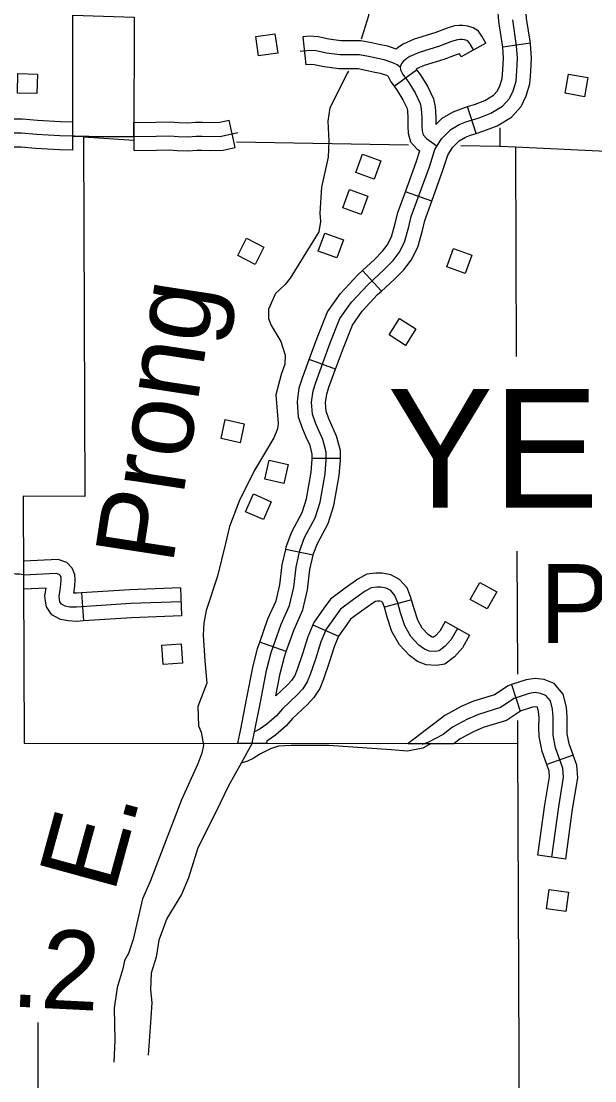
# Model space of a CAD drawing. Extents: x 1370130 to 1380143, y 377636 to 380256.
# Drawn here: x 1377471.8 to 1377557.8, y 379033.5 to 379192.2 of the extents above; entities that cross this region are included whole.
import ezdxf

# ---------------------------------------------------------------- set-up
doc = ezdxf.new("R2010")
doc.units = 0
for name, color, linetype in [('Level 32', 7, 'Continuous'), ('Level 34', 7, 'Continuous'), ('Level 35', 7, 'Continuous'), ('Level 4', 7, 'Continuous'), ('Level 48', 7, 'Continuous'), ('Level 5', 7, 'Continuous'), ('Level 56', 7, 'Continuous'), ('Level 6', 7, 'Continuous')]:
    doc.layers.add(name, color=color, linetype=linetype)

msp = doc.modelspace()

# ---------------------------------------------------------------- linework, layer by layer
at = {"layer": 'Level 32'}
for p, q in [((1377513.99, 379189.81), (1377514.45, 379185.63)), ((1377541.41, 379188.89), (1377537.74, 379186.86)), ((1377548.1, 379188.9), (1377543.95, 379188.27)), ((1377527.68, 379182.43), (1377531.06, 379184.91)), ((1377539.97, 379175.38), (1377538.7, 379179.39)), ((1377503.89, 379173.26), (1377502.97, 379177.36)), ((1377533.32, 379165.21), (1377529.37, 379166.65)), ((1377525.8, 379151.76), (1377522.97, 379154.87)), ((1377518.92, 379140.09), (1377514.97, 379141.54)), ((1377519.63, 379126.7), (1377515.43, 379126.7)), ((1377515.54, 379112.2), (1377511.44, 379113.09)), ((1377480.86, 379106.57), (1377481.14, 379102.38)), ((1377495.68, 379107.35), (1377495.85, 379103.15)), ((1377530.3, 379105.54), (1377526.25, 379104.43)), ((1377515.52, 379101.78), (1377519.36, 379100.09)), ((1377535.35, 379102.29), (1377539, 379100.22)), ((1377511.53, 379097.79), (1377507.56, 379099.18)), ((1377545.27, 379092.84), (1377546.57, 379088.84)), ((1377554.52, 379082.27), (1377550.57, 379080.87)), ((1377553.4, 379066.71), (1377549.24, 379067.28))]:
    msp.add_line(p, q, dxfattribs=at)
for points in [[(1377543.95, 379188.27), (1377543.36, 379192.13), (1377543.17, 379194.94), (1377543.22, 379197.67), (1377543.5, 379201.64), (1377543.76, 379203.58)], [(1377548.1, 379188.9), (1377547.54, 379192.6), (1377547.37, 379195.05), (1377547.41, 379197.48), (1377547.68, 379201.21), (1377547.92, 379203)], [(1377506.43, 379084.05), (1377506.79, 379085.76), (1377507.65, 379090.2), (1377508.56, 379094.96), (1377509.25, 379097.63), (1377510.74, 379101.89), (1377512.01, 379104.7), (1377512.64, 379107.42), (1377513, 379110.41), (1377513.55, 379112.9), (1377514.27, 379114.85), (1377515.86, 379117.79), (1377516.63, 379120.15), (1377517.35, 379124.4), (1377517.53, 379126.53), (1377517.53, 379127.62), (1377517.03, 379129.52), (1377516.99, 379129.52), (1377515.95, 379131.88), (1377515.45, 379133.33), (1377515.31, 379135.14), (1377515.54, 379136.82), (1377515.95, 379138.09), (1377518.12, 379144.03), (1377519.57, 379147.65), (1377521.29, 379150.1), (1377523.73, 379152.72), (1377526.22, 379154.99), (1377527.54, 379156.35), (1377528.44, 379157.53), (1377529.26, 379159.11), (1377529.89, 379161.38), (1377530.25, 379162.92), (1377532.97, 379170.39), (1377533.81, 379172.97), (1377534.76, 379174.56), (1377536.17, 379175.96), (1377537.44, 379176.69), (1377538.43, 379177.1), (1377540.42, 379177.73), (1377542.19, 379178.41), (1377543.91, 379179.45), (1377544.95, 379180.59), (1377545.5, 379181.76), (1377545.95, 379183.21), (1377546.08, 379184.75), (1377546.17, 379186.66), (1377546.04, 379188.51), (1377545.45, 379192.36)], [(1377541.41, 379188.89), (1377540.83, 379189.94), (1377540.31, 379190.67), (1377539.51, 379191.16), (1377538.74, 379191.45), (1377537.97, 379191.53), (1377537.42, 379191.53), (1377536.74, 379191.46), (1377535.62, 379191.11), (1377533.77, 379190.42), (1377530.69, 379189.46), (1377529.05, 379188.73), (1377528.35, 379188.29), (1377527.99, 379187.99)], [(1377527.99, 379187.99), (1377526.74, 379188.42), (1377525.67, 379188.62), (1377524.28, 379188.93), (1377522.7, 379189.22), (1377520.99, 379189.22), (1377519.72, 379189.26), (1377517.9, 379189.48), (1377516.31, 379189.81), (1377515.04, 379189.92), (1377513.99, 379189.81)], [(1377539.57, 379187.87), (1377539.05, 379188.82), (1377538.85, 379189.1), (1377538.58, 379189.27), (1377538.25, 379189.39), (1377537.86, 379189.43), (1377537.54, 379189.43), (1377537.17, 379189.39), (1377536.3, 379189.12), (1377534.46, 379188.43), (1377531.43, 379187.49), (1377530.04, 379186.87), (1377529.59, 379186.59), (1377529.1, 379186.18), (1377528.81, 379185.85), (1377528.69, 379185.6), (1377528.61, 379185.28), (1377528.65, 379184.87), (1377528.98, 379184.21), (1377529.88, 379182.98), (1377530.86, 379181.43), (1377531.59, 379179.87), (1377531.76, 379179.05), (1377531.84, 379177.74), (1377531.84, 379176.47), (1377531.88, 379175.74), (1377532.04, 379175.16), (1377532.54, 379174.63), (1377533.23, 379174.1), (1377534.12, 379173.48)], [(1377528.61, 379185.28), (1377528.15, 379185.64), (1377527.51, 379185.93), (1377526.2, 379186.38), (1377525.24, 379186.57), (1377523.86, 379186.87), (1377522.51, 379187.12), (1377520.96, 379187.12), (1377519.56, 379187.16), (1377517.56, 379187.41), (1377516, 379187.73), (1377515.06, 379187.81), (1377513.59, 379187.65)], [(1377538.7, 379179.39), (1377539.73, 379179.71), (1377541.26, 379180.3), (1377542.57, 379181.09), (1377543.18, 379181.76), (1377543.53, 379182.52), (1377543.88, 379183.62), (1377543.99, 379184.9), (1377544.07, 379186.63), (1377543.95, 379188.28), (1377543.95, 379188.27)], [(1377539.97, 379175.38), (1377541.12, 379175.75), (1377543.12, 379176.52), (1377545.25, 379177.81), (1377546.72, 379179.41), (1377547.46, 379181.01), (1377548.02, 379182.8), (1377548.18, 379184.61), (1377548.28, 379186.68), (1377548.13, 379188.75), (1377548.1, 379188.9)], [(1377537.74, 379186.86), (1377537.49, 379187.29), (1377536.98, 379187.14), (1377535.14, 379186.44), (1377532.17, 379185.52), (1377531.03, 379185.02), (1377531, 379185), (1377531.06, 379184.91)], [(1377526.75, 379183.97), (1377525.66, 379184.35), (1377524.82, 379184.51), (1377523.44, 379184.81), (1377522.32, 379185.02), (1377520.92, 379185.02), (1377519.41, 379185.06), (1377517.21, 379185.33), (1377515.7, 379185.65), (1377515.09, 379185.7), (1377514.45, 379185.63)], [(1377531.06, 379184.91), (1377531.61, 379184.17), (1377532.7, 379182.44), (1377533.6, 379180.54), (1377533.84, 379179.33), (1377533.94, 379177.81), (1377533.94, 379176.71)], [(1377526.75, 379183.97), (1377527.18, 379183.11), (1377527.68, 379182.43)], [(1377527.68, 379182.43), (1377528.14, 379181.8), (1377529.01, 379180.41), (1377529.59, 379179.21), (1377529.67, 379178.78), (1377529.74, 379177.68), (1377529.74, 379176.42), (1377529.8, 379175.39), (1377530.16, 379174.11), (1377531.11, 379173.07), (1377531.53, 379172.76)], [(1377484.13, 379174.88), (1377477.62, 379175), (1377474.11, 379175.2), (1377471.88, 379175.4), (1377470.16, 379175.4), (1377468.52, 379175.4), (1377467.04, 379175.25), (1377465.26, 379175.3), (1377459.43, 379175.99), (1377449.15, 379177.33), (1377442.98, 379178.22), (1377439.17, 379178.81), (1377437.05, 379179.35), (1377435.32, 379180), (1377433.7, 379180.91)], [(1377533.94, 379176.71), (1377534.88, 379177.65), (1377536.51, 379178.58), (1377537.71, 379179.07), (1377538.7, 379179.39)], [(1377479.53, 379172.87), (1377479.54, 379177.07), (1377477.7, 379177.1), (1377474.26, 379177.29), (1377471.98, 379177.5), (1377470.16, 379177.5), (1377469.36, 379177.5)], [(1377488.72, 379172.8), (1377488.67, 379177), (1377492, 379177.05), (1377494.13, 379177.1), (1377495.42, 379177), (1377496.78, 379176.96), (1377497.94, 379177.05), (1377498.96, 379177.05), (1377500.16, 379177), (1377501.57, 379177.05), (1377502.97, 379177.36)], [(1377488.7, 379174.9), (1377492.04, 379174.95), (1377494.07, 379175), (1377495.31, 379174.9), (1377496.84, 379174.85), (1377498.02, 379174.95), (1377498.91, 379174.95), (1377500.15, 379174.9), (1377501.83, 379174.95), (1377504.25, 379175.5)], [(1377533.32, 379165.21), (1377534.95, 379169.71), (1377535.74, 379172.1), (1377536.43, 379173.26), (1377537.45, 379174.28), (1377538.36, 379174.8), (1377539.15, 379175.12), (1377539.97, 379175.38)], [(1377479.53, 379172.87), (1377477.54, 379172.9), (1377473.96, 379173.1), (1377471.79, 379173.3), (1377470.16, 379173.3), (1377469.36, 379173.3)], [(1377488.72, 379172.8), (1377492.09, 379172.85), (1377494.01, 379172.9), (1377495.19, 379172.81), (1377496.89, 379172.75), (1377498.11, 379172.85), (1377498.87, 379172.85), (1377500.14, 379172.8), (1377502.09, 379172.86), (1377503.89, 379173.26)], [(1377529.37, 379166.65), (1377530.98, 379171.08), (1377531.53, 379172.76)], [(1377522.97, 379154.87), (1377524.76, 379156.5), (1377525.95, 379157.72), (1377526.66, 379158.66), (1377527.29, 379159.88), (1377527.86, 379161.9), (1377528.24, 379163.52), (1377529.37, 379166.65)], [(1377525.8, 379151.76), (1377527.69, 379153.48), (1377529.13, 379154.97), (1377530.22, 379156.4), (1377531.22, 379158.34), (1377531.93, 379160.85), (1377532.27, 379162.32), (1377533.32, 379165.21)], [(1377514.97, 379141.54), (1377516.16, 379144.78), (1377517.71, 379148.66), (1377519.65, 379151.42), (1377522.26, 379154.22), (1377522.97, 379154.87)], [(1377518.92, 379140.09), (1377520.08, 379143.27), (1377521.43, 379146.64), (1377522.92, 379148.77), (1377525.21, 379151.23), (1377525.8, 379151.76)], [(1377515.43, 379126.7), (1377515.43, 379127.36), (1377515.1, 379128.65), (1377514.53, 379129.9), (1377513.99, 379131.11), (1377513.37, 379132.9), (1377513.2, 379135.2), (1377513.48, 379137.28), (1377513.96, 379138.77), (1377514.97, 379141.54)], [(1377519.63, 379126.7), (1377519.63, 379127.89), (1377519.07, 379130.06), (1377518.36, 379131.62), (1377517.9, 379132.65), (1377517.52, 379133.76), (1377517.42, 379135.08), (1377517.6, 379136.35), (1377517.93, 379137.4), (1377518.92, 379140.09)], [(1377511.44, 379113.09), (1377511.53, 379113.49), (1377512.35, 379115.71), (1377513.92, 379118.62), (1377514.58, 379120.65), (1377515.27, 379124.67), (1377515.43, 379126.62), (1377515.43, 379126.7)], [(1377515.54, 379112.2), (1377515.57, 379112.31), (1377516.19, 379113.98), (1377517.79, 379116.96), (1377518.67, 379119.64), (1377519.44, 379124.14), (1377519.63, 379126.44), (1377519.63, 379126.7)], [(1377507.56, 379099.18), (1377508.79, 379102.67), (1377510.01, 379105.37), (1377510.57, 379107.78), (1377510.93, 379110.76), (1377511.44, 379113.09)], [(1377480.86, 379106.57), (1377480.1, 379106.52), (1377479.69, 379106.54), (1377479.73, 379106.76), (1377479.83, 379107.61), (1377479.91, 379108.51), (1377479.87, 379109.35), (1377479.47, 379110.3), (1377478.65, 379111.12), (1377477.38, 379111.59), (1377472.17, 379111.34), (1377472.18, 379107.14)], [(1377511.53, 379097.79), (1377512.69, 379101.11), (1377514.01, 379104.02), (1377514.71, 379107.05), (1377515.08, 379110.06), (1377515.54, 379112.2)], [(1377495.76, 379105.25), (1377488.22, 379104.96), (1377480.12, 379104.42), (1377479.12, 379104.46), (1377478.41, 379104.59), (1377477.84, 379104.88), (1377477.6, 379105.25), (1377477.55, 379105.57), (1377477.5, 379106.06), (1377477.65, 379107.05), (1377477.74, 379107.83), (1377477.81, 379108.55), (1377477.79, 379108.88), (1377477.7, 379109.11), (1377477.49, 379109.31), (1377477.05, 379109.47), (1377472.17, 379109.24)], [(1377530.3, 379105.54), (1377530.25, 379105.73), (1377529.62, 379107.31), (1377528.49, 379108.59), (1377527.18, 379109.29), (1377525.9, 379109.52), (1377524.97, 379109.52), (1377523.62, 379109.37), (1377522.24, 379108.61), (1377520.37, 379107.26), (1377518.14, 379105.65), (1377517.16, 379104.27), (1377515.68, 379102.15), (1377515.52, 379101.78)], [(1377481.14, 379102.38), (1377480.13, 379102.31), (1377478.89, 379102.37), (1377477.73, 379102.57), (1377476.39, 379103.27), (1377475.59, 379104.47), (1377475.46, 379105.31), (1377475.38, 379106.12), (1377475.56, 379107.3), (1377472.18, 379107.14)], [(1377495.68, 379107.35), (1377488.11, 379107.05), (1377480.86, 379106.57)], [(1377537.17, 379101.25), (1377536.22, 379099.58), (1377535.32, 379098.58), (1377534.41, 379097.9), (1377533.91, 379097.81), (1377532.92, 379097.86), (1377532.24, 379098.13), (1377531.38, 379098.76), (1377530.2, 379100.03), (1377529.29, 379101.66), (1377528.66, 379103.57), (1377528.25, 379105.06), (1377527.8, 379106.19), (1377527.17, 379106.92), (1377526.49, 379107.28), (1377525.72, 379107.42), (1377525.08, 379107.42), (1377524.27, 379107.33), (1377523.36, 379106.83), (1377521.6, 379105.56), (1377519.65, 379104.15), (1377518.88, 379103.07), (1377517.52, 379101.12), (1377516.71, 379099.26), (1377515.94, 379096.81), (1377515.12, 379094.37), (1377514.67, 379093.24), (1377513.99, 379092.19), (1377513.18, 379091.29), (1377510.96, 379089.2), (1377510.05, 379088.16), (1377508.6, 379086.94), (1377507.61, 379086.21), (1377506.79, 379085.76)], [(1377526.26, 379104.39), (1377525.98, 379105.08), (1377525.84, 379105.25), (1377525.79, 379105.27), (1377525.53, 379105.32), (1377525.2, 379105.32), (1377524.92, 379105.28), (1377524.49, 379105.05), (1377522.82, 379103.85), (1377521.16, 379102.66), (1377520.6, 379101.86), (1377519.36, 379100.09), (1377519.36, 379100.09)], [(1377535.35, 379102.29), (1377534.51, 379100.82), (1377533.9, 379100.14), (1377533.61, 379099.93), (1377533.37, 379099.94), (1377533.27, 379099.98), (1377532.78, 379100.34), (1377531.91, 379101.27), (1377531.23, 379102.51), (1377530.67, 379104.17), (1377530.3, 379105.54)], [(1377539, 379100.22), (1377537.93, 379098.34), (1377536.74, 379097.02), (1377535.28, 379095.92), (1377534.06, 379095.7), (1377532.47, 379095.78), (1377531.21, 379096.28), (1377529.97, 379097.19), (1377528.49, 379098.79), (1377527.36, 379100.81), (1377526.65, 379102.96), (1377526.25, 379104.43)], [(1377495.85, 379103.15), (1377488.33, 379102.86), (1377481.14, 379102.38)], [(1377515.52, 379101.78), (1377514.74, 379100), (1377513.94, 379097.46), (1377513.15, 379095.09), (1377512.8, 379094.21), (1377512.32, 379093.48), (1377511.67, 379092.76), (1377509.97, 379091.16)], [(1377504.28, 379084.05), (1377504.73, 379086.18), (1377505.59, 379090.6), (1377506.51, 379095.42), (1377507.23, 379098.24), (1377507.56, 379099.18)], [(1377519.36, 379100.09), (1377518.68, 379098.52), (1377517.94, 379096.17), (1377517.1, 379093.65), (1377516.54, 379092.26), (1377515.66, 379090.91), (1377514.68, 379089.82), (1377512.47, 379087.75), (1377511.83, 379087)], [(1377509.97, 379091.16), (1377510.61, 379094.5), (1377511.26, 379097.02), (1377511.53, 379097.79)], [(1377545.27, 379092.84), (1377544.78, 379092.68), (1377542.7, 379091.31), (1377539.59, 379090.35), (1377537.75, 379089.57), (1377535.28, 379088.23), (1377529.81, 379084.03), (1377536.7, 379084.02)], [(1377554.52, 379082.27), (1377554.51, 379082.32), (1377553.91, 379083.95), (1377553.61, 379085.49), (1377553.59, 379086.55), (1377553.6, 379088), (1377553.51, 379089.48), (1377553.01, 379091.42), (1377551.68, 379093), (1377550.17, 379093.58), (1377548.81, 379093.77), (1377547.45, 379093.55), (1377545.27, 379092.84)], [(1377551.32, 379067), (1377552.35, 379074.52), (1377553.08, 379078.96), (1377552.98, 379080.34), (1377552.53, 379081.6), (1377551.88, 379083.38), (1377551.51, 379085.27), (1377551.49, 379086.54), (1377551.5, 379087.94), (1377551.43, 379089.15), (1377551.1, 379090.43), (1377550.42, 379091.23), (1377549.64, 379091.53), (1377548.83, 379091.64), (1377547.94, 379091.5), (1377545.69, 379090.77), (1377543.61, 379089.39), (1377540.31, 379088.37), (1377538.66, 379087.68), (1377536.43, 379086.46), (1377535.02, 379085.38), (1377532.73, 379084.16), (1377531.85, 379083.88)], [(1377550.57, 379080.87), (1377550.56, 379080.89), (1377549.85, 379082.82), (1377549.42, 379085.05), (1377549.39, 379086.53), (1377549.4, 379087.89), (1377549.34, 379088.82), (1377549.18, 379089.44), (1377549.16, 379089.47), (1377549.11, 379089.48), (1377548.86, 379089.52), (1377548.44, 379089.45), (1377546.57, 379088.84)], [(1377546.61, 379088.86), (1377544.51, 379087.48), (1377541.03, 379086.4), (1377539.57, 379085.78), (1377537.58, 379084.7), (1377536.7, 379084.02)], [(1377511.83, 379087), (1377511.53, 379086.66), (1377509.9, 379085.29), (1377508.64, 379084.37)], [(1377508.64, 379084.37), (1377508.58, 379084.04), (1377504.28, 379084.05)], [(1377553.4, 379066.71), (1377554.42, 379074.21), (1377555.2, 379078.86), (1377555.05, 379080.78), (1377554.52, 379082.27)], [(1377549.24, 379067.28), (1377550.27, 379074.83), (1377550.97, 379079.05), (1377550.91, 379079.9), (1377550.57, 379080.87)]]:
    msp.add_lwpolyline(points, dxfattribs=at)
at = {"layer": 'Level 34'}
for points in [[(1377479.53, 379174.97), (1377482.85, 379174.9), (1377488.7, 379174.9)], [(1377472.17, 379109.28), (1377471.57, 379109.36), (1377470.95, 379109.4), (1377470.06, 379109.42), (1377468.43, 379109.33), (1377466.23, 379109.37), (1377461.06, 379109.67), (1377457.96, 379109.77), (1377456.63, 379109.72), (1377455.23, 379109.65)], [(1377506.43, 379084.05), (1377504.78, 379081.1), (1377502.89, 379077.69), (1377500.97, 379073.73), (1377498.27, 379068.39), (1377496.89, 379063.89), (1377495.81, 379061.43), (1377493.65, 379057.83), (1377492.45, 379054.59), (1377492.03, 379052.01), (1377491.31, 379049.61), (1377491.19, 379047.15), (1377491.37, 379045.23), (1377491.25, 379042.94), (1377490.85, 379037.33)], [(1377533.25, 379084.02), (1377531.97, 379083.3), (1377529.7, 379082.89), (1377527.23, 379083.06), (1377517.91, 379083.74), (1377512.28, 379083.74), (1377510.36, 379083.62), (1377509.16, 379083.2), (1377507.66, 379082.48), (1377506.58, 379081.76), (1377505.74, 379081.4), (1377504.78, 379081.1)]]:
    msp.add_lwpolyline(points, dxfattribs=at)
at = {"layer": 'Level 35'}
for points in [[(1377489.53, 379238.19), (1377490.22, 379236.59), (1377492.04, 379234.13), (1377494.34, 379232.72), (1377499.35, 379230.67), (1377501.83, 379229.09), (1377503.32, 379227.92), (1377504.29, 379226.81), (1377505.48, 379224.9), (1377507.04, 379221.46), (1377507.98, 379219.82), (1377509.19, 379218.11), (1377510.83, 379216.46), (1377512.72, 379214.22), (1377517.12, 379208.28), (1377518.11, 379206.17), (1377519.61, 379201.85), (1377520.22, 379200.69), (1377522.74, 379196.89), (1377523.44, 379195.62), (1377523.86, 379194.2), (1377523.86, 379192.99), (1377522.86, 379189.8), (1377522.73, 379189.47)], [(1377520.83, 379184.7), (1377520.72, 379184.42), (1377518.04, 379179.2), (1377517.78, 379177.23), (1377517.89, 379174.23), (1377517.8, 379171.82), (1377516.8, 379167.33), (1377516.57, 379163.43), (1377516.65, 379162.19), (1377516.4, 379160.62), (1377512.13, 379153.68), (1377511.34, 379152.74), (1377509.9, 379151.39), (1377508.88, 379149.07), (1377508.85, 379147.69), (1377509.24, 379146.72), (1377510.72, 379144.2), (1377511.35, 379142.16), (1377511.32, 379140.84), (1377510.77, 379139.29), (1377509.96, 379136.21), (1377510.3, 379131.92), (1377510.2, 379131.14), (1377509.69, 379129.81), (1377506.73, 379124.86), (1377504.47, 379120.3), (1377503.03, 379116.51), (1377502.43, 379113.97)], [(1377502.43, 379113.97), (1377501.21, 379109.09), (1377499.52, 379103.92), (1377499.16, 379102.06), (1377499.06, 379100.26), (1377499.31, 379096.39), (1377499.65, 379093.06), (1377498.26, 379089.58), (1377498.38, 379086.69), (1377498.79, 379085.74), (1377499.14, 379083.76), (1377498.88, 379082.58), (1377498.27, 379080.96), (1377495.82, 379075.58), (1377491.13, 379063.36), (1377489.97, 379060.75), (1377488.58, 379054.69), (1377487.89, 379052.6), (1377487.27, 379051.52), (1377487.04, 379050.28), (1377486.2, 379047.51), (1377485.75, 379044.39), (1377485.85, 379039.54), (1377485.71, 379036.29)]]:
    msp.add_lwpolyline(points, dxfattribs=at)
at = {"layer": 'Level 4'}
for points in [[(1377529.84, 379173.63), (1377504.05, 379174.06)], [(1377687.01, 379166.75), (1377684.84, 379166.69), (1377545.86, 379173.3), (1377543.53, 379173.41), (1377537.66, 379173.5)]]:
    msp.add_lwpolyline(points, dxfattribs=at)
at = {"layer": 'Level 48'}
msp.add_lwpolyline([(1377474.3, 379042.24), (1377474.3, 379030.65), (1377472.23, 379020.85)], dxfattribs=at)
at = {"layer": 'Level 5'}
for points in [[(1377543.54, 379176.19), (1377543.53, 379173.41)], [(1377545.86, 379173.3), (1377545.97, 379141.98)], [(1377546.08, 379112.81), (1377546.15, 379094.4)], [(1377546.18, 379087.46), (1377546.19, 379084.01)]]:
    msp.add_lwpolyline(points, dxfattribs=at)
at = {"layer": 'Level 56'}
for points in [[(1377509.84, 379190.28), (1377510.26, 379187.4), (1377507.37, 379186.98), (1377506.95, 379189.86)], [(1377471.26, 379181.42), (1377471.33, 379184.34), (1377474.25, 379184.26), (1377474.18, 379181.35)], [(1377553.31, 379181.38), (1377553.82, 379184.25), (1377556.7, 379183.74), (1377556.19, 379180.87)], [(1377521.97, 379169.52), (1377522.97, 379172.26), (1377525.72, 379171.26), (1377524.72, 379168.52)], [(1377520.02, 379164.24), (1377521.02, 379166.98), (1377523.76, 379165.98), (1377522.77, 379163.24)], [(1377516.33, 379157.72), (1377517.33, 379160.46), (1377520.08, 379159.46), (1377519.08, 379156.72)], [(1377508.19, 379158.34), (1377506.87, 379155.74), (1377504.26, 379157.08), (1377505.59, 379159.67)], [(1377535.57, 379155.41), (1377536.57, 379158.15), (1377539.31, 379157.15), (1377538.32, 379154.41)], [(1377530.95, 379146.1), (1377529.38, 379143.64), (1377526.92, 379145.21), (1377528.48, 379147.67)], [(1377504.6, 379129.04), (1377501.76, 379129.68), (1377502.39, 379132.53), (1377505.24, 379131.89)], [(1377511.17, 379122.97), (1377508.33, 379123.6), (1377508.96, 379126.46), (1377511.81, 379125.82)], [(1377508.11, 379117.56), (1377505.44, 379118.73), (1377506.61, 379121.41), (1377509.28, 379120.23)], [(1377543.06, 379106.72), (1377541.65, 379104.17), (1377539.1, 379105.58), (1377540.51, 379108.13)], [(1377493.07, 379095.85), (1377492.87, 379098.76), (1377495.78, 379098.97), (1377495.99, 379096.06)], [(1377553.39, 379058.89), (1377550.5, 379059.28), (1377550.9, 379062.18), (1377553.79, 379061.78)]]:
    msp.add_lwpolyline(points, close=True, dxfattribs=at)
at = {"layer": 'Level 6'}
msp.add_lwpolyline([(1377479.54, 379177.07), (1377479.55, 379193.08), (1377488.72, 379192.79), (1377488.7, 379174.32), (1377481.17, 379174.82), (1377481.37, 379121.03), (1377472.13, 379121.04), (1377472.27, 379084.08), (1377546.19, 379084.01), (1377546.45, 379013.69)], dxfattribs=at)

# ---------------------------------------------------------------- texts
at = {"layer": 'Level 35'}
for s, rotation, p in [('Prong', 81.2795, (1377494.51, 379110.65)), ('E.', 74.6747, (1377485.73, 379061.42))]:
    msp.add_text(s, height=11.827, rotation=rotation, dxfattribs=at).set_placement(p)
at = {"layer": 'Level 48'}
msp.add_text('0.2', height=11.827, rotation=357.1364, dxfattribs=at).set_placement((1377461.39, 379045.1))
at = {"layer": 'Level 6'}
for s, height, p in [('YELLVILLE', 17.741, (1377526.69, 379119.35)), ('Pop. 1,204', 11.827, (1377549.48, 379099.05))]:
    msp.add_text(s, height=height, dxfattribs=at).set_placement(p)

doc.saveas('drawing.dxf')
